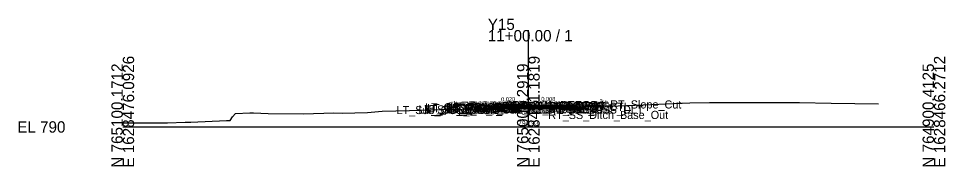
# Model space of a CAD drawing. Extents: x -26 to 203, y -10 to 2522.
# Drawn here: x -25.7 to 202.8, y 1990.3 to 2026.6 of the extents above; entities that cross this region are included whole.
import ezdxf

# ---------------------------------------------------------------- set-up
doc = ezdxf.new("R2010")
doc.units = 0
for name, color, linetype in [('Default', 7, 'Continuous'), ('Exist Cross Section Cell', 7, 'Continuous'), ('Exist XS Center Line Elevation Label', 7, 'Continuous'), ('Exist XS Ground Line', 7, 'Continuous'), ('Prop CMT Concrete Structures', 7, 'Continuous'), ('Prop CMT Pvmt Course 1', 7, 'Continuous'), ('Prop CMT Pvmt Course 1 Wedge', 7, 'Continuous'), ('Prop CMT Pvmt Course 2', 7, 'Continuous'), ('Prop CMT Pvmt Course 2 Wedge', 7, 'Continuous'), ('Prop CMT Pvmt Course 3', 7, 'Continuous'), ('Prop CMT Pvmt Surface', 7, 'Continuous'), ('Prop CMT Pvmt Surface Shoulder', 7, 'Continuous'), ('Prop CMT Pvmt Wedge Surface 2', 7, 'Continuous'), ('Prop CMT Pvmt Wedge Surface 3', 7, 'Continuous'), ('Prop CMT Shld Paved Course 1', 7, 'Continuous'), ('Prop CMT Shld Paved Course 2', 7, 'Continuous'), ('Prop CMT Shld Paved Course 3', 7, 'Continuous'), ('Prop CMT Slope Grass', 7, 'Continuous'), ('Prop CMT Subgrade Earthwork', 7, 'Continuous'), ('Prop XS SE Text', 7, 'Continuous'), ('Prop XS Side Slope Text', 7, 'Continuous'), ('Scratch_Level_0', 7, 'Continuous')]:
    doc.layers.add(name, color=color, linetype=linetype)

msp = doc.modelspace()

# ---------------------------------------------------------------- linework, layer by layer
at = {"layer": 'Exist Cross Section Cell'}
for p, q in [((100, 2000), (100, 2023.84)), ((0, 2000), (100, 2000)), ((100, 2000), (200, 2000))]:
    msp.add_line(p, q, dxfattribs=at)
at = {"layer": 'Exist XS Ground Line'}
msp.add_lwpolyline([(0, 2000.99), (1.87, 2001), (3.13, 2001), (6.31, 2001.04), (7.7, 2001.04), (11.02, 2001.04), (15.38, 2001.18), (16.78, 2001.22), (25.59, 2001.57), (26.45, 2001.62), (27.08, 2002.47), (27.8, 2003.35), (31.37, 2003.45), (31.83, 2003.46), (32.2, 2003.44), (35.85, 2003.29), (44.57, 2003.23), (52.07, 2003.45), (54.13, 2003.41), (60.37, 2003.55), (63.95, 2003.86), (70.68, 2004.01), (78.79, 2004.27), (88.59, 2004.49), (91.29, 2004.54), (91.9, 2004.6), (94.05, 2004.88), (94.45, 2004.88), (94.81, 2004.89), (100, 2004.93), (101.22, 2004.94), (106.19, 2004.96), (110.59, 2004.96), (122.16, 2005.23), (128.33, 2005.44), (139.79, 2005.95), (144.66, 2005.98), (159.36, 2005.98), (166.88, 2006.04), (174.65, 2005.88), (186.32, 2005.65)], dxfattribs=at)
at = {"layer": 'Prop CMT Concrete Structures'}
for points in [[(88.14, 2005.24), (88.14, 2004.66), (90.14, 2004.66)], [(90.14, 2005.24), (89.14, 2005.16), (88.14, 2005.24)], [(90.14, 2004.66), (90.14, 2005.24)], [(111.87, 2005.36), (111.87, 2004.78), (109.87, 2004.78)], [(109.87, 2005.36), (110.87, 2005.28), (111.87, 2005.36)], [(109.87, 2004.78), (109.87, 2005.36)]]:
    msp.add_lwpolyline(points, dxfattribs=at)
at = {"layer": 'Prop CMT Pvmt Course 1'}
for points in [[(100, 2005.44), (90.14, 2005.24)], [(90.14, 2005.24), (90.14, 2004.99)], [(90.14, 2004.99), (100, 2005.19)], [(100, 2005.44), (94.05, 2005.32)], [(100, 2005.31), (100, 2005.44)], [(100, 2005.19), (100, 2005.44)], [(100, 2005.44), (106.19, 2005.39)], [(100, 2005.31), (100, 2005.44)], [(100, 2005.44), (109.87, 2005.36)], [(100, 2005.19), (100, 2005.44)], [(109.87, 2005.11), (100, 2005.19)], [(109.87, 2005.36), (109.87, 2005.11)]]:
    msp.add_lwpolyline(points, dxfattribs=at)
at = {"layer": 'Prop CMT Pvmt Course 1 Wedge'}
for points in [[(100, 2005.19), (94.81, 2005.08), (94.45, 2005.08), (94.05, 2005.07)], [(100, 2005.31), (100, 2005.19)], [(100, 2005.19), (100, 2005.31)], [(106.19, 2005.14), (101.22, 2005.18), (100, 2005.19)]]:
    msp.add_lwpolyline(points, dxfattribs=at)
at = {"layer": 'Prop CMT Pvmt Course 2'}
for points in [[(100, 2005.19), (90.14, 2004.99)], [(90.14, 2004.99), (90.14, 2004.66)], [(90.14, 2004.66), (100, 2004.85)], [(100, 2004.85), (100, 2005.19)], [(100, 2004.85), (100, 2005.19)], [(100, 2005.19), (109.87, 2005.11)], [(109.87, 2004.78), (100, 2004.85)], [(109.87, 2005.11), (109.87, 2004.78)]]:
    msp.add_lwpolyline(points, dxfattribs=at)
at = {"layer": 'Prop CMT Pvmt Course 2 Wedge'}
for points in [[(94.05, 2005.07), (94.45, 2005.08), (94.81, 2005.08), (100, 2005.19)], [(100, 2004.93), (94.81, 2004.89), (94.45, 2004.88), (94.05, 2004.88)], [(100, 2005.19), (100, 2004.93)], [(100, 2005.19), (101.22, 2005.18), (106.19, 2005.14)], [(100, 2004.93), (100, 2005.19)], [(106.19, 2004.96), (101.22, 2004.94), (100, 2004.93)]]:
    msp.add_lwpolyline(points, dxfattribs=at)
at = {"layer": 'Prop CMT Pvmt Course 3'}
msp.add_line((111.87, 2004.78), (112.37, 2004.78), dxfattribs=at)
for points in [[(100, 2004.85), (90.14, 2004.66)], [(90.14, 2004.66), (90.14, 2004.32)], [(90.14, 2004.32), (100, 2004.52)], [(100, 2004.52), (100, 2004.85)], [(100, 2004.85), (109.87, 2004.78)], [(100, 2004.52), (100, 2004.85)], [(109.87, 2004.45), (100, 2004.52)], [(109.87, 2004.78), (109.87, 2004.45)]]:
    msp.add_lwpolyline(points, dxfattribs=at)
at = {"layer": 'Prop CMT Pvmt Surface'}
for points in [[(100, 2005.44), (90.14, 2005.24)], [(100, 2005.44), (94.05, 2005.32)], [(100, 2005.44), (109.87, 2005.36)], [(100, 2005.44), (106.19, 2005.39)]]:
    msp.add_lwpolyline(points, dxfattribs=at)
at = {"layer": 'Prop CMT Pvmt Surface Shoulder'}
for points in [[(90.14, 2005.24), (90.14, 2005.24)], [(109.87, 2005.36), (109.87, 2005.36)]]:
    msp.add_lwpolyline(points, dxfattribs=at)
at = {"layer": 'Prop CMT Pvmt Wedge Surface 2'}
for points in [[(100, 2005.19), (94.05, 2005.07)], [(100, 2005.19), (100, 2005.44)], [(100, 2005.19), (100, 2005.44)], [(100, 2005.19), (100, 2005.44)], [(100, 2005.19), (100, 2005.44)], [(100, 2005.19), (106.19, 2005.14)]]:
    msp.add_lwpolyline(points, dxfattribs=at)
at = {"layer": 'Prop CMT Pvmt Wedge Surface 3'}
for points in [[(100, 2004.85), (94.05, 2004.74)], [(100, 2004.85), (100, 2005.44)], [(100, 2004.85), (100, 2005.44)], [(100, 2004.85), (100, 2005.44)], [(100, 2004.85), (100, 2005.44)], [(100, 2004.85), (106.19, 2004.81)]]:
    msp.add_lwpolyline(points, dxfattribs=at)
at = {"layer": 'Prop CMT Shld Paved Course 1'}
for points in [[(90.14, 2005.24), (90.14, 2005.24)], [(90.14, 2004.99), (90.14, 2005.24)], [(109.87, 2005.36), (109.87, 2005.36)], [(109.87, 2005.11), (109.87, 2005.36)]]:
    msp.add_lwpolyline(points, dxfattribs=at)
at = {"layer": 'Prop CMT Shld Paved Course 2'}
for p, q in [((88.14, 2004.66), (90.14, 2004.66)), ((111.87, 2004.78), (109.87, 2004.78))]:
    msp.add_line(p, q, dxfattribs=at)
for points in [[(90.14, 2004.66), (90.14, 2004.99)], [(109.87, 2004.78), (109.87, 2005.11)]]:
    msp.add_lwpolyline(points, dxfattribs=at)
at = {"layer": 'Prop CMT Shld Paved Course 3'}
for p, q in [((87.3, 2004.32), (90.14, 2004.32)), ((112.71, 2004.44), (109.87, 2004.45))]:
    msp.add_line(p, q, dxfattribs=at)
for points in [[(90.14, 2004.66), (88.14, 2004.66), (87.64, 2004.66), (87.3, 2004.32)], [(90.14, 2004.32), (90.14, 2004.66)], [(109.87, 2004.45), (109.87, 2004.78)], [(109.87, 2004.78), (112.37, 2004.78), (112.37, 2004.78), (112.71, 2004.44)]]:
    msp.add_lwpolyline(points, dxfattribs=at)
at = {"layer": 'Prop CMT Slope Grass'}
for points in [[(88.14, 2005.24), (83.14, 2005.34), (80.01, 2004.3)], [(111.87, 2005.36), (116.87, 2005.46), (117.87, 2005.13)]]:
    msp.add_lwpolyline(points, dxfattribs=at)
at = {"layer": 'Prop CMT Subgrade Earthwork'}
for p, q in [((87.3, 2004.32), (86.34, 2005.28)), ((90.14, 2004.32), (87.3, 2004.32)), ((109.87, 2004.45), (112.71, 2004.44)), ((112.71, 2004.44), (113.67, 2005.4))]:
    msp.add_line(p, q, dxfattribs=at)
for points in [[(100, 2004.52), (90.14, 2004.32)], [(100, 2004.52), (109.87, 2004.45)]]:
    msp.add_lwpolyline(points, dxfattribs=at)

# ---------------------------------------------------------------- texts
at = {"layer": 'Default'}
msp.add_text('-', height=0.0001, dxfattribs=at).set_placement((0, 2000))
at = {"layer": 'Exist Cross Section Cell'}
for s, p in [('Y15', (90, 2023.84)), ('11+00.00 / 1', (90, 2021.04)), ('EL 790', (-26, 1998.6))]:
    msp.add_text(s, height=2.8, dxfattribs=at).set_placement(p)
for s, p in [('E 1628476.0926', (2.8, 1990)), ('E 1628471.1819', (102.8, 1990)), ('E 1628466.2712', (202.8, 1990)), ('N 765100.1712', (0, 1990)), ('N 765000.2919', (100, 1990)), ('N 764900.4125', (200, 1990))]:
    msp.add_text(s, height=2.8, rotation=90, dxfattribs=at).set_placement(p)
at = {"layer": 'Exist XS Center Line Elevation Label'}
msp.add_text('794.93', height=1.2, dxfattribs=at).set_placement((97.47, 2000.33))
at = {"layer": 'Prop XS SE Text'}
for s, rotation, p in [('0.020', 1.1458, (93.3, 2006.3)), ('0.008', 359.5703, (103.2, 2006.41))]:
    msp.add_text(s, height=1, rotation=rotation, dxfattribs=at).set_placement(p)
at = {"layer": 'Prop XS Side Slope Text'}
for rotation, p in [(341.5651, (117.36, 2006.01)), (18.4349, (80.64, 2004.98))]:
    msp.add_text('3:1', height=1, rotation=rotation, dxfattribs=at).set_placement(p)
at = {"layer": 'Scratch_Level_0'}
for s, p in [('RT_Slope_Cut', (120.19, 2004.54)), ('LT_Sub_OSS_DLT', (67.51, 2003.17)), ('LT_Sub_Trench_Out', (72.91, 2003.3)), ('LT_Slope_Fill', (74.27, 2003.38)), ('LT_GS_OS_CTL', (74.51, 2003.84)), ('LT_PS3_Shelf_Out', (75.03, 2003.64)), ('LT_PS3_OEOP', (79.78, 2003.65)), ('LT_PS2_OEOP', (80.12, 2003.99)), ('LT_Sub_OEOT', (80.22, 2003.32)), ('LT_PV2_OEOT', (80.31, 2003.99)), ('LT_PV3_OEOT', (80.31, 2003.66)), ('LT_PV1_OEOT', (80.88, 2004.24)), ('LT_PS1_OEOP', (80.94, 2004.24)), ('LT_PV2_OEEOP_W', (81.47, 2004.07)), ('LT_PV3_OEEOP_W', (81.47, 2003.74)), ('LT_PV1_OEEOP_W', (82.04, 2004.19)), ('LT_PV1_OEEOP', (83.93, 2004.32)), ('RT_PV1_PGL_W', (89.84, 2004.31)), ('LT_PV1_PGL_W', (89.89, 2004.31)), ('RT_PV2_OEEOP_W', (93.56, 2004.14)), ('RT_PV3_OEEOP_W', (93.56, 2003.81)), ('Sub_PGL', (93.81, 2003.52)), ('PV2_PGL', (93.91, 2004.19)), ('PV3_PGL', (93.91, 2003.85)), ('RT_PV1_OEEOP_W', (94.13, 2004.27)), ('PV1_PGL', (94.47, 2004.44)), ('RT_Sub_Trench_Out', (95.46, 2003.42)), ('RT_PV1_OEEOP', (96.02, 2004.39)), ('RT_PS3_Shelf_Out', (96.9, 2003.76)), ('RT_Sub_OEOT', (99.9, 2003.45)), ('RT_PV2_OEOT', (99.99, 2004.11)), ('RT_PV3_OEOT', (99.99, 2003.78)), ('RT_PS2_OEOP', (100.31, 2004.11)), ('RT_PV1_OEOT', (100.56, 2004.36)), ('RT_PS1_OEOP', (100.62, 2004.36)), ('RT_PS3_OEOP', (100.65, 2003.77)), ('RT_GS_OS_CTL', (104.19, 2003.96)), ('RT_Sub_OSS_DLT', (104.9, 2003.29)), ('RT_SS_Ditch_Base_Out', (104.9, 2001.96))]:
    msp.add_text(s, height=2, dxfattribs=at).set_placement(p)

doc.saveas('drawing.dxf')
